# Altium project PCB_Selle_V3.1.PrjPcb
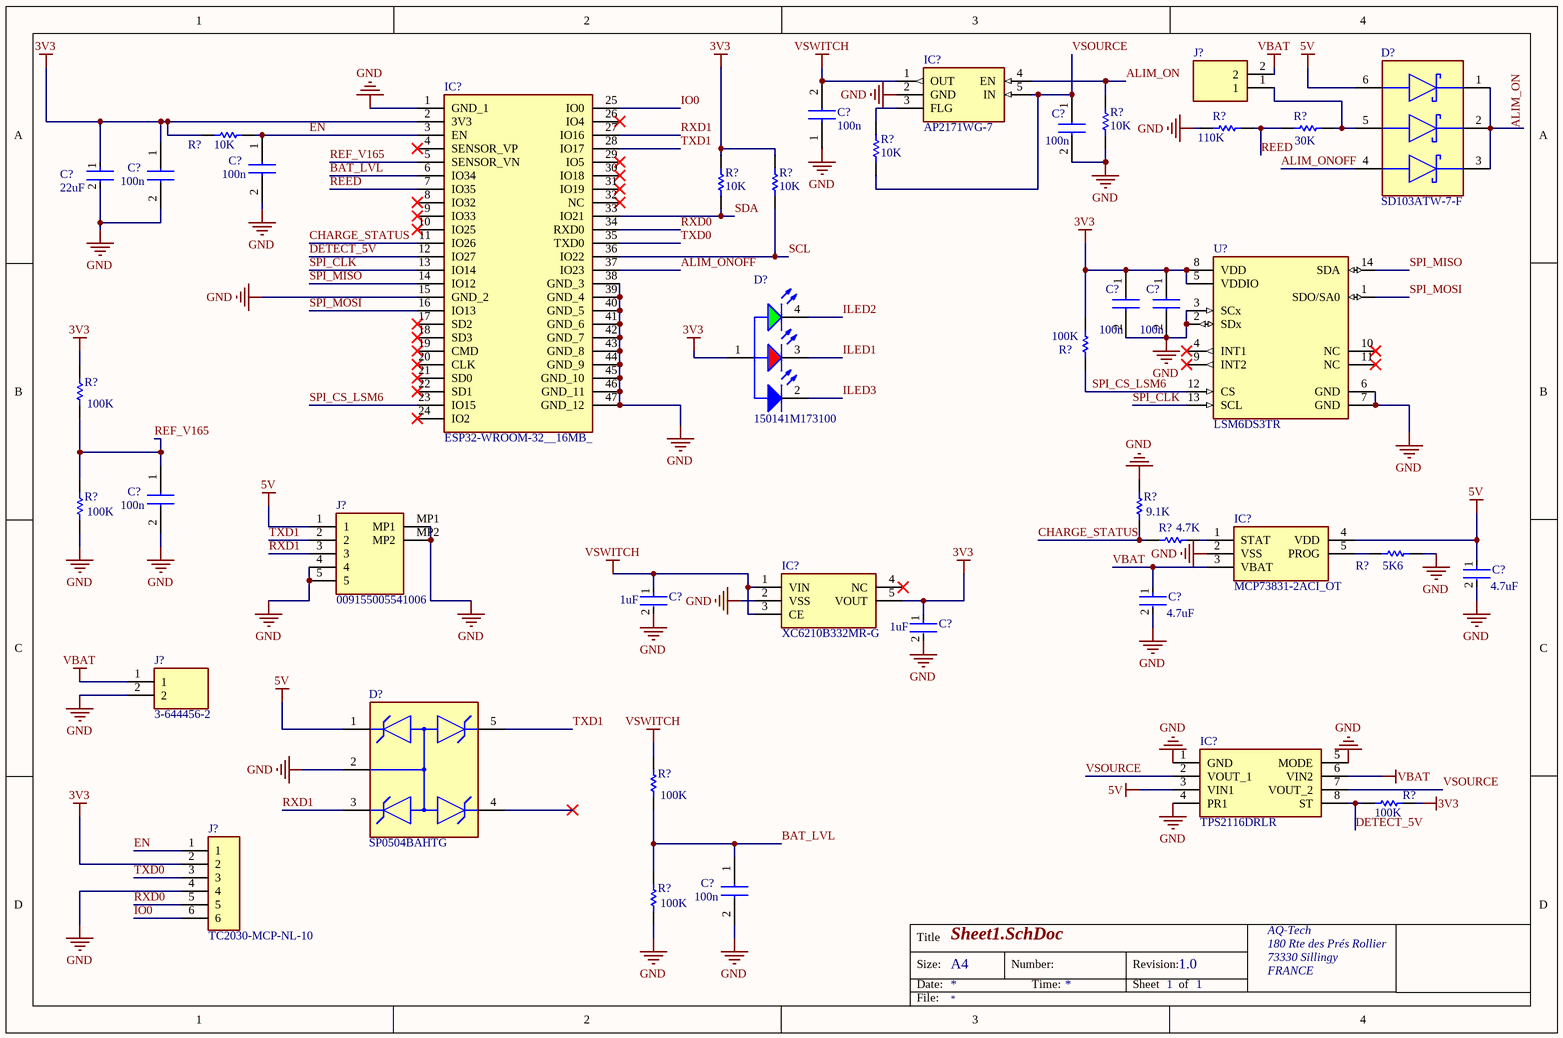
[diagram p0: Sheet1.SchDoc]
CAGE_CODE: ?????; CONTRACT_NUMBER: <CONTRACT NO>; DOC_NO_ASSY_DWG: <ASSY DWG NO>; DOC_NO_BOM: <BOM DOC NO>; DOC_NO_FAB_DWG: <FAB DWG NO>; DOC_NO_SCH_DWG: <SCH DWG NO>; PCB_2_DEC_TOL: +/-.01; PCB_3_DEC_TOL: +/-.010; PCB_ANG_TOL: +/-1/2; PCB_ASSEMBLY_NO: <PCB ASSY NO>; PCB_CHECKER: - -----; PCB_CHECKER_APP_DATE: --/--/----; PCB_DESIGNER: - -----; PCB_DESIGNER_APP_DATE: --/--/----; PCB_DWG_NO: <PCB DWG NO>; PCB_ENGINEER: - -----; PCB_ENGINEER_APP_DATE: --/--/----; PCB_PART_NUMBER: <PCB PN>; PCB_REV: A; SCH_REV: A
1 sheet, 42 parts. Net scope: global (net labels, ports and power ports of the same name join across sheets).
Board files: PCB1.PcbDoc, CAMtastic1.PcbDoc, CAMtastic2.PcbDoc

## Sheet Sheet1.SchDoc: DEV-09-17 MERE
size A4; ENG_APP_DATE: --/--/--; DSN_APP_DATE: --/--/--; CHK_APP_DATE: --/--/--; Date: 22/11/2017; Organization: Altium Limited; Address1: L3, 12a Rodborough Rd; Address2: Frenchs Forest; Address3: NSW; Address4: Australia 2086; Revision: 1.0; SheetNumber: 1; SheetTotal: 1; PageSetup: Record=PageOptions¦CenterHorizontal=True¦CenterVertical=True¦PrintScale=0.97¦XCorrection=1.00¦YCorrection=1.00¦PrintKind=0¦BorderSize=5000000¦LeftOffset=0¦BottomOffset=0¦Orientation=2¦PaperLength=1000¦PaperWidth=1000¦Scale=100¦PaperSource=7¦PrintQuality=-3¦MediaType=1¦DitherType=10¦PaperKind=A4¦PrintScaleMode=1

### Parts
(Parts that share a designator on the sheet are numbered #1, #2 ... from top to bottom, then left to right.)
C?#1  Capacitance: 100n  [CAPC1608X90N]
C?#2  Capacitance: 100n  [CAPC1608X90N]
C?#3  Capacitance: 100n  [CAPC1608X90N]
C?#4  Capacitance: 100n  [CAPC1608X90N]
C?#5  Capacitance: 22uF  [FP-GRM188-0_2-IPC_C]  (hidden comment: GRM188R61A226ME15D)
C?#6  Capacitance: 100n  [CAPC1608X90N]
C?#7  Capacitance: 100n  [CAPC1608X90N]
C?#8  Capacitance: 100n  [CAPC1608X90N]
C?#9  Capacitance: 4.7uF  [FP-CL828-IPC_C]  (hidden comment: CL05A475KP5NRNC)
C?#10  Capacitance: 1uF  [FP-CL511-IPC_C]  (hidden comment: CL05A105KP5NNNC)
C?#11  Capacitance: 4.7uF  [FP-CL828-IPC_C]  (hidden comment: CL05A475KP5NRNC)
C?#12  Capacitance: 1uF  [FP-CL511-IPC_C]  (hidden comment: CL05A105KP5NNNC)
C?#13  Capacitance: 100n  [CAPC1608X90N]
D?#1  SD103ATW-7-F  [FP-SOT363-IPC_A]
D?#2  150141M173100  [WL-SFTW_3528_150141M173100]
D?#3  SP0504BAHTG  [FP-SP0504BAHTG-MFG]
IC?#1  AP2171WG-7  [SOT95P282X130-5N]
IC?#2  ESP32-WROOM-32__16MB_  [ESP32WROOM3216MB]
IC?#3  MCP73831-2ACI_OT  [SOT95P270X145-5N]
IC?#4  XC6210B332MR-G  [SOT95P280X130-5N]
IC?#5  TPS2116DRLR  [SOTFL50P160X60-8N]
J?#1  3-644456-2  [HDRV2W67P0X254_1X2_478X234X1029P]  (value not drawn)
J?#2  009155005541006  [009155005541006]
J?#3  3-644456-2  [HDRV2W67P0X254_1X2_478X234X1029P]
J?#4  TC2030-MCP-NL-10  [TC2030MCPNL10]
R?#1  Resistance: 10K  [RESC1005X40X25ML05T05]  (hidden comment: ERJ-2GEJ103X)
R?#2  Resistance: 110K  [RESC1005X40X25LL05T10]  (hidden comment: RC0402FR-07110KL)
R?#3  Resistance: 30K  [RESC1005X40X25LL05T10]  (hidden comment: RC0402FR-0730KL)
R?#4  Resistance: 10K  [RESC1005X40X25ML05T05]  (hidden comment: ERJ-2GEJ103X)
R?#5  Resistance: 10K  [RESC1005X40X25ML05T05]  (hidden comment: ERJ-2GEJ103X)
R?#6  Resistance: 10K  [RESC1005X40X25ML05T05]  (hidden comment: ERJ-2GEJ103X)
R?#7  Resistance: 10K  [RESC1005X40X25ML05T05]  (hidden comment: ERJ-2GEJ103X)
R?#8  Resistance: 100K  [RESC1005X40X25NL05T10]  (hidden comment: RC0402FR-07100KL)
R?#9  Resistance: 100K  [RESC1005X40X25NL05T10]  (hidden comment: RC0402FR-07100KL)
R?#10  Resistance: 100K  [RESC1005X40X25NL05T10]  (hidden comment: RC0402FR-07100KL)
R?#11  Resistance: 9.1K  [RESC1005X40X25NL05T10]  (hidden comment: RC0402FR-079K1L)
R?#12  Resistance: 4.7K  [RESC1005X40X25NL05T10]  (hidden comment: RC0402FR-074K7L)
R?#13  Resistance: 5K6  [RESC1005X40X25LL05T10]  (hidden comment: RC0402JR-075K6L)
R?#14  Resistance: 100K  [RESC1005X40X25NL05T10]  (hidden comment: RC0402FR-07100KL)
R?#15  Resistance: 100K  [RESC1005X40X25NL05T10]  (hidden comment: RC0402FR-07100KL)
R?#16  Resistance: 100K  [RESC1005X40X25NL05T10]  (hidden comment: RC0402FR-07100KL)
U?  LSM6DS3TR  [FP-LGA-14-DM00249496-MFG]

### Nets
3V3: C?#3.1 C?#5.1 C?#6.1 C?#7.1 C?#12.1 D?#2.1(A) IC?#2.2(3V3) IC?#4.5(VOUT) J?#4.2 R?#5.2 R?#6.1 R?#7.1 R?#8.2 R?#9.2 R?#15.1 U?.5(VDDIO) U?.8(VDD)
5V: C?#9.1 D?#1.6(1_ANODE) D?#3.1 IC?#3.4(VDD) IC?#5.3(VIN1) J?#2.1
GND: C?#1.2 C?#2.2 C?#3.2 C?#4.1 C?#5.2 C?#6.2 C?#7.2 C?#8.2 C?#9.2 C?#10.2 C?#11.2 C?#12.2 C?#13.2 D?#3.2 IC?#1.2(GND) IC?#2.1(GND_1) IC?#2.15(GND_2) IC?#2.38(GND_3) IC?#2.39(GND_4) IC?#2.40(GND_5) IC?#2.41(GND_6) IC?#2.42(GND_7) IC?#2.43(GND_8) IC?#2.44(GND_9) IC?#2.45(GND_10) IC?#2.46(GND_11) IC?#2.47(GND_12) IC?#3.2(VSS) IC?#4.2(VSS) IC?#5.1(GND) IC?#5.4(PR1) IC?#5.5(MODE) J?#2.4 J?#2.5 J?#2.MP1 J?#2.MP2 J?#3.2 J?#4.4 R?#1.2 R?#2.1 R?#10.1 R?#11.2 R?#13.2 R?#16.1 U?.2(SDx) U?.3(SCx) U?.6(GND) U?.7(GND)
VBAT: C?#11.1 IC?#3.3(VBAT) IC?#5.6(VIN2) J?#1.2 J?#3.1
VSWITCH: C?#4.2 C?#10.1 IC?#1.1(OUT) IC?#4.1(VIN) IC?#4.3(CE) R?#14.2
ALIM_ON: D?#1.1(1_CATHODE) D?#1.2(2_CATHODE) D?#1.3(3_CATHODE) IC?#1.4(EN) R?#1.1
ALIM_ONOFF: D?#1.4(3_ANODE) IC?#2.37(IO23)
BAT_LVL: C?#13.1 IC?#2.6(IO34) R?#14.1 R?#16.2
CHARGE_STATUS: IC?#2.11(IO26) R?#11.1 R?#12.1
DETECT_5V: IC?#2.12(IO27) IC?#5.8(ST) R?#15.2
EN: C?#2.1 IC?#2.3(EN) J?#4.1 R?#5.1
ILED1: D?#2.3(K)
ILED2: D?#2.4(K)
ILED3: D?#2.2(K)
IO0: IC?#2.25(IO0) J?#4.6
REED: IC?#2.7(IO35) R?#2.2 R?#3.1
REF_V165: C?#8.1 IC?#2.5(SENSOR_VN) R?#9.1 R?#10.2
RXD0: IC?#2.34(RXD0) J?#4.5
RXD1: D?#3.3 IC?#2.27(IO16) J?#2.3
SCL: IC?#2.36(IO22) R?#7.2
SDA: IC?#2.33(IO21) R?#6.2
SPI_CLK: IC?#2.13(IO14) U?.13(SCL)
SPI_CS_LSM6: IC?#2.23(IO15) R?#8.1 U?.12(CS)
SPI_MISO: IC?#2.14(IO12) U?.14(SDA)
SPI_MOSI: IC?#2.16(IO13) U?.1(SDO/SA0)
TXD0: IC?#2.35(TXD0) J?#4.3
TXD1: D?#3.5 IC?#2.28(IO17) J?#2.2
VSOURCE: C?#1.1 IC?#1.5(IN) IC?#5.2(VOUT_1) IC?#5.7(VOUT_2) R?#4.2
NetD?#1_5: D?#1.5(2_ANODE) J?#1.1 R?#3.2
NetIC?#1_3: IC?#1.3(FLG) R?#4.1
NetIC?#3_1: IC?#3.1(STAT) R?#12.2
NetIC?#3_5: IC?#3.5(PROG) R?#13.1

Not connected (* = marked no-connect by the designer): D?#3 4*; IC?#2 4(SENSOR_VP)* 8(IO32)* 9(IO33)* 10(IO25)* 17(SD2)* 18(SD3)* 19(CMD)* 20(CLK)* 21(SD0)* 22(SD1)* 24(IO2)* 26(IO4)* 29(IO5)* 30(IO18)* 31(IO19)* 32(NC)*; IC?#4 4(NC)*; U? 4(INT1)* 9(INT2)* 10(NC)* 11(NC)*

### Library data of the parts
C?#1-C?#4 C?#6-C?#8 C?#13 = CL10B104KB8NNNC: Capacitor; Manufacturer_Name: SAMSUNG
C?#5 = CMP-2000-06337-3: Chip Multilayer Ceramic Capacitors for General Purpose, 0603, 22uF, X5R, 15%, 20%, 10V
C?#9 C?#11 = CMP-13271-001251-1: Cap Ceramic 4.7uF 10V X5R ±10% SMD 0402 +85°C Paper T/R
C?#10 C?#12 = CMP-13271-001936-1: Cap Ceramic 1uF 10V X5R ±10% SMD 0402 +85°C Paper T/R
D?#1 = CMP-12790-000076-1: DIODE ARRAY SCHOTTKY 40V SOT363; Current Rating: 350mA; Forward Voltage: 500mV; Peak Non-Repetitive Surge Current: 1A; Peak Reverse Current: 5uA; Power Rating: 200mW; Reverse Recovery Time: 10ns; Capacitance: 50pF; Average Rectified Current: 175mA
D?#2 = CMP-1431-00001-2: NexarPartId: 29717795; Forward Current: 100mA; Peak Wavelength: 465nm; Viewing Angle: 120°; Color: Green, Red; Max Reverse Voltage (DC): 5V; Forward Voltage: 3.2V; Dominant Wavelength: 520nm; Test Current: 20mA; Power Dissipation: 72mW; Wavelength: 470nm; Lens Style: Clear, Round; Luminous Intensity: 230mcd
D?#3 = CMP-08607-000010-1: TVS DIODE 5.5V 8.5V SOT23-5; Manufacturer: Littelfuse; Direction: Unidirectional; Number Of Channels: 4; Value: 30pF; Standoff Height: 0mm
IC?#1 = AP2171WG-7: Integrated Circuit; Manufacturer_Name: Diodes Inc.
IC?#2 = ESP32-WROOM-32__16MB_: Integrated Circuit; Manufacturer_Name: Espressif Systems; Manufacturer_Part_Number: ESP32-WROOM-32 (16MB)
IC?#3 = MCP73831-2ACI_OT: Integrated Circuit; Manufacturer_Name: Microchip; Manufacturer_Part_Number: MCP73831-2ACI/OT
IC?#4 = XC6210B332MR-G: Integrated Circuit; Manufacturer_Name: Torex
IC?#5 = TPS2116DRLR: Integrated Circuit; Manufacturer_Name: Texas Instruments
J?#1 J?#3 = 3-644456-2: Connector; Manufacturer_Name: TE Connectivity
J?#2 = 009155005541006: Connector; Manufacturer_Name: AVX
J?#4 = TC2030-MCP-NL-10: Connector; Manufacturer_Name: Tag Connect
R?#1 R?#4-R?#7 = CMP-2002-00433-1: Manufacturer: Panasonic
R?#2 = CMP-2002-07022-1: Manufacturer: Yageo / Phycomp
R?#3 = CMP-2002-07602-1: Manufacturer: Yageo / Phycomp
R?#8-R?#10 R?#14-R?#16 = CMP-2002-07343-1: Manufacturer: Yageo / Phycomp
R?#11 = CMP-2002-07017-1: Manufacturer: Yageo / Phycomp
R?#12 = CMP-1011-00586-2: Manufacturer: Yageo / Phycomp
R?#13 = CMP-2002-08026-1: Manufacturer: Yageo / Phycomp
U? = CMP-2000-05193-2: IMU ACCEL/GYRO I2C/SPI 14VFLGA; Manufacturer: STMicroelectronics; Sensor Type: Temperature,Accelerometer,Gyroscope; Gyro Range: 125/250/500/1000/2000°/s; Min Supply Voltage: 1.62V; Operating Supply Current: 9-900uA; Accel Range: 2/4/8/16g; Max Supply Voltage: 3.6V; Sensor Output: I2C,SPI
